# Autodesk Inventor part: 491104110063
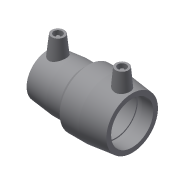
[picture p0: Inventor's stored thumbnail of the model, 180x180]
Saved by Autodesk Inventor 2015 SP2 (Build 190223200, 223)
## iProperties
Created: 2017-06
Part Number: 491104110063
Material: Generic
Description: PLASSON REDUCING COUPLER 110-63
Document SubType Name: Modeling
Designer: KIM
Mass: 54.8237 g
Surface Area: 155.252 cm^2
Volume: 54.8237 cm^3
Density: 1 g/cm^3
Appearance: Default
Author: KIM
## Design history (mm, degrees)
derived "491104.ipt"
feature "Solid1::491104.ipt"
tag "TaggingFeature1"
body "Solid1"
other parameters: "d_1" = 63, "L_" = 161, "L_2" = 57, "D_1" = 82, "A_1" = 61, "d_2" = 12, "L_1" = 78, "A_" = 84, "D_" = 139, "d0" = 161, "d2" = 82, "d3" = 57, "d4" = 34.2, "d5" = 73.8, "d7" = 63, "d8" = 168 deg, "d10" = 22.8, "d11" = 7.6, "d13" = 161, "d14" = 17.6296, "d15" = 57, "d18" = 63, "d19" = 2.85, "d20" = 168 deg, "d22" = 108.92847, "d25" = 135 deg, "d29" = 61, "d30" = 15, "d31" = 64.4, "d34" = 6 deg, "d35" = 15, "d38" = 26.35, "d39" = 5 deg, "d41" = 4, "d42" = 14, "d43" = 0, "d45" = 4, "d46" = 14, "d47" = 0, "d48" = 82, "d50" = 139, "d52" = 56.7, "d53" = 31.2, "d54" = 10.4, "d55" = 168 deg, "d56" = 46.8, "d57" = 78, "d58" = 125.1, "d59" = 2.85, "d60" = 135 deg, "d61" = 84, "d62" = 15, "d64" = 4, "d66" = 5 deg, "d67" = 14, "d68" = 0, "d69" = 64.4, "d70" = 82, "d71" = 139, "d73" = 130.66, "d76" = 2.85, "d77" = 168 deg, "d79" = 2.85, "d80" = 78, "d81" = 56.7, "d82" = 77.08, "d83" = 120 deg, "d88" = 15, "d89" = 23.5, "d90" = 5 deg, "d92" = 4, "d93" = 14, "d94" = 0, "d95" = 3, "d96" = 0, "d97" = 3, "d98" = 0, "d99" = 16.53, "d100" = 4.1325, "d101" = 74.7676, "d102" = 20 deg, "d103" = 22.62, "d104" = 5.655, "d105" = 126.7402, "d106" = 3.60705, "d107" = 3, "d108" = 0, "d109" = 3, "d110" = 0
